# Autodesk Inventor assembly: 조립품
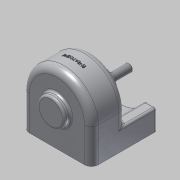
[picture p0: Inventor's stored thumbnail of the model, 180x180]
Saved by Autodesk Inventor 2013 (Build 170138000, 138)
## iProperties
Created: 2015-02
Part Number: 조립품
Document SubType Name: Assembly
Designer: Administrator
Author: Administrator
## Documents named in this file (10)
- C:\Users\Administrator\Desktop\450216V1002\조립품.iam
- C:\Users\Administrator\Desktop\450216V1002\본체.ipt
- C:\Users\Administrator\Desktop\450216V1002\축.ipt
- C:\Users\Administrator\Desktop\450216V1002\키4x4.ipt
- C:\Users\Administrator\Desktop\450216V1002\키5x5.ipt
- C:\Users\Administrator\Desktop\450216V1002\베어링 6001.ipt
- C:\Users\Administrator\Desktop\450216V1002\V-벨트풀리.ipt
- C:\Users\Administrator\Desktop\450216V1002\스퍼기어.ipt
- C:\Users\Administrator\Desktop\450216V1002\축커버.ipt
- C:\Users\Administrator\Desktop\450216V1002\M3x0.5.ipt
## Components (2 placed, 2 different names)
1. V-벨트풀리:1
2. M3x0.5:1
